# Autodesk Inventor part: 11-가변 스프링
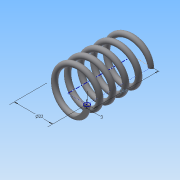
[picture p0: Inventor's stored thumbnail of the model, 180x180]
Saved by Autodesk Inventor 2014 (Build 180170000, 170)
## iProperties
Created: 2015-09
Part Number: 11-가변 스프링
Material: 강철, 탄소
Document SubType Name: Modeling
Designer: study
Density: 1 g/cm^3
Appearance: 반연마
Mass: 2.3997 g
Surface Area: 32.5491 cm^2
Volume: 2.3997 cm^3
Author: study
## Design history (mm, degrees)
sketch "스케치1"
  geometry: L1 (0, 0)-(11, 0); L2 (11, 0)-(11, 36.411); L3 (11, 36.411)-(0, 36.411); L4 (0, 36.411)-(0, 0); C1 r 1.5 at (11, 0)
  constraints: 8 end point, 2 parallel, 1 centre point, 1 coincident, 1 horizontal, 1 perpendicular
  dimensions: "d0" = 22 diameter of L2 L4; "d1" = 36.4112 distance of L1.end L2.end (derived); "d2" = 3 diameter of C1
feature "코일1" sketch "스케치1" pitch "d3" = 10; turns "d5" = 5; dims "d4" = 36.4112 (= d1), "d6" = 0, angle "d7" = 90 deg, angle "d8" = 90 deg, "d9" = 0, "d10" = 0
node "작업 평면1"
sketch "스케치2"
  geometry: L1 (-12.5, 0)-(-9.5, 0) reference; 1 further point
  constraints: 1 horizontal alignment
extrude "돌출1" cut sketch "스케치2" stored distance "d12" = 10; taper "d13" = 0 deg
node "작업 평면2"
sketch "스케치3"
  geometry: L1 (-9.5, 0)-(-12.5, 0) reference; 1 further point
  constraints: 1 horizontal alignment
extrude "돌출2" cut sketch "스케치3" stored distance "d15" = 10; taper "d16" = 0 deg
node "솔리드1"
node "절단 모서리 투영1"
node "절단 모서리 투영2"
other parameters: "d11" = 0, "d14" = 36.4112 (= d1)
